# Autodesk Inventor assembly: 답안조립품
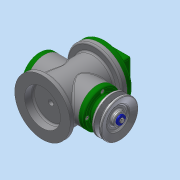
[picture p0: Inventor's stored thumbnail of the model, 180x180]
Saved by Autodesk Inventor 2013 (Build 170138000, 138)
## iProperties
Created: 2018-02
Part Number: 답안조립품
Document SubType Name: Assembly
Designer: dgall
Author: dgall
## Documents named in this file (18)
- C:\Users\dgall\Desktop\480207V1012\답안조립품.iam
- C:\Users\dgall\Desktop\480207V1012\본체.ipt
- C:\Users\dgall\Desktop\480207V1012\링크.ipt
- C:\Users\dgall\Desktop\480207V1012\슬라이더.ipt
- C:\Users\dgall\Desktop\480207V1012\클레비스 핀 6 x 22.ipt
- 클레비스 핀 6 x 22.ipt
- C:\Users\dgall\Desktop\480207V1012\편심축.ipt
- C:\Users\dgall\Desktop\480207V1012\E-링.ipt
- C:\Users\dgall\Desktop\480207V1012\베어링 17 x 40 x 12.ipt
- C:\Users\dgall\Desktop\480207V1012\뒤커버.ipt
- C:\Users\dgall\Desktop\480207V1012\앞커버.ipt
- C:\Users\dgall\Desktop\480207V1012\오일 실 17 30 8.ipt
- C:\Users\dgall\Desktop\480207V1012\V-벨트풀리.ipt
- C:\Users\dgall\Desktop\480207V1012\와셔 4x16.ipt
- C:\Users\dgall\Desktop\480207V1012\키 4 x 4 x 12.ipt
- C:\Users\dgall\Desktop\480207V1012\볼트 M4 x 8.ipt
- C:\Users\dgall\Desktop\480207V1012\볼트 M4 x 10.ipt
- C:\Users\dgall\Desktop\480207V1012\덮개.ipt
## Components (2 placed, 2 different names)
1. E-링:1
2. V-벨트풀리:1
